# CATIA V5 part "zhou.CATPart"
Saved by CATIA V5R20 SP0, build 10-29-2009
Part number: part2
Material "Crisp Blue": density 7860 kg/m3, Young's modulus 2e+11 Pa, Poisson ratio 0.266
Material "Ground": density 10000 kg/m3, Young's modulus 7e+10 Pa, Poisson ratio 0.27
Bounding box of the stored display mesh (mm): x -150 to 0, y -99.659 to 100.557, z -60 to 40
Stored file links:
  C:\Users\asus\Desktop\180211401-刘畅\新建文件夹\zhou.CATPart
  D:\Program Files\Dassault Systemes\B20\win_b64\startup\materials\Catalog.CATMaterial
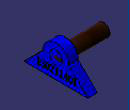
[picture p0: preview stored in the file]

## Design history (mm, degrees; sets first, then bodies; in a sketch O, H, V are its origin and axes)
Body1 (main body), material "Ground"
  Sketch1 on yz-plane, origin (0, 0, 0), H (0, 1, 0), V (0, 0, 1)
    circle A1 centre (0, 0) radius 20
    radius A1 = 20
  Pad1: profile Sketch1, direction (-1, 0, 0), length 150
Body2, material "Crisp Blue"
  Sketch2 on yz-plane, origin (0, 0, 0), H (0, 1, 0), V (0, 0, 1)
    arc A1 centre (0, 0) radius 40 from (40, 0) to (-40, 0) ccw
    point P1 (-40, 0)
    point P2 (40, 0)
    line L1 (-99.6591, -60) -> (100.5569, -60)
    line L2 (100.5569, -60) -> (40, 0)
    point P5 (40, 0)
    point P6 (-40, 0)
    line L3 (-40, 0) -> (-99.6591, -60)
    radius A1 = 40
    horizontal: L1 H
    coincidence: L2 P2, P6 A1, P6 H, P5 P2, P1 P6
  Pad2: profile Sketch2, direction (-1, 0, 0), length 30
Body3
  Sketch3 on yz-plane, origin (0, 0, 0), H (0, 1, 0), V (0, 0, 1)
    polyline C1
    polyline C2
    polyline C3
    polyline C4
    polyline C5
    polyline C6
    polyline C7
    polyline C8
    polyline C9
    polyline C10
    polyline C11
    polyline C12
    polyline C13
    polyline C14
  Pocket1: profile Sketch3, direction (-1, 0, 0), length 1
